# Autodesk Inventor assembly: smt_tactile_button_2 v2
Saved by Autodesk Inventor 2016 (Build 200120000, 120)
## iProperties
Created: 2016-09
Part Number: smt_tactile_button_2 v2
Document SubType Name: Assembly
Designer: Administrator
Author: Administrator
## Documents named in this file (5)
- c:\worker\convert-fusion-aug-2016\tmp\job-1\19\output\files\b1646d38-3d95-4128-a552-c87d2d1b62c9\smt_tactile_button_2 v2.iam
- c:\worker\convert-fusion-aug-2016\tmp\job-1\19\output\files\b1646d38-3d95-4128-a552-c87d2d1b62c9\Component43.ipt
- c:\worker\convert-fusion-aug-2016\tmp\job-1\19\output\files\b1646d38-3d95-4128-a552-c87d2d1b62c9\Component44.ipt
- c:\worker\convert-fusion-aug-2016\tmp\job-1\19\output\files\b1646d38-3d95-4128-a552-c87d2d1b62c9\Component45.ipt
- c:\worker\convert-fusion-aug-2016\tmp\job-1\19\output\files\b1646d38-3d95-4128-a552-c87d2d1b62c9\Component46.ipt
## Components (4 placed, 4 different names)
1. Component43:1
2. Component44:1
3. Component45:1
4. Component46:1
